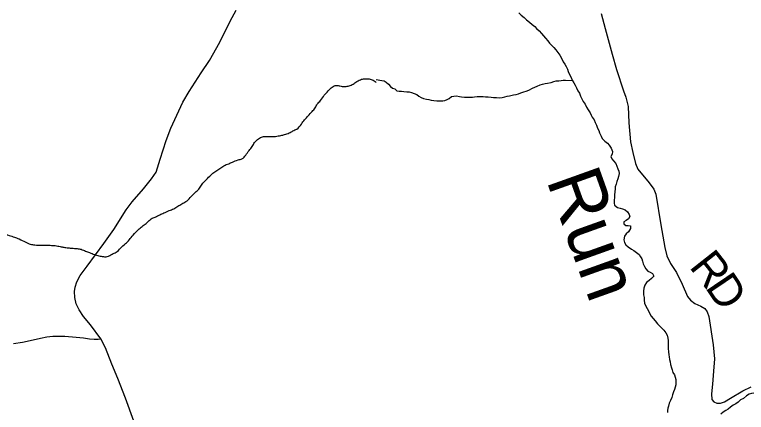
# Model space of a CAD drawing. Extents: x -13.7 to 34, y 0 to 32.3.
# Drawn here: x 28.447 to 29.728, y 16.87 to 17.566 of the extents above; entities that cross this region are included whole.
import ezdxf

# ---------------------------------------------------------------- set-up
doc = ezdxf.new("R2010")
doc.units = 0
for name, color, linetype in [('GM_X_County_Road', 7, 'Continuous'), ('GM_X_Minor_River', 7, 'Continuous'), ('GM_X_Minor_River_Text', 7, 'Continuous'), ('GM_X_Township_Road', 7, 'Continuous'), ('GM_X_Township_Road_Text', 7, 'Continuous')]:
    doc.layers.add(name, color=color, linetype=linetype)

msp = doc.modelspace()

# ---------------------------------------------------------------- linework, layer by layer
at = {"layer": 'GM_X_County_Road'}
msp.add_lwpolyline([(28.6553, 16.8546), (28.641, 16.8947), (28.6272, 16.9288), (28.617, 16.954), (28.6055, 16.9827), (28.5974, 16.9986), (28.5797, 17.0227), (28.567, 17.0378), (28.5598, 17.049), (28.5546, 17.0596), (28.5518, 17.0705), (28.5512, 17.0811), (28.5525, 17.0888), (28.5555, 17.0984), (28.5614, 17.1091), (28.5736, 17.1258), (28.6027, 17.165), (28.6205, 17.19), (28.6417, 17.2243), (28.6525, 17.2383), (28.6721, 17.2607), (28.6865, 17.2785), (28.6942, 17.2902), (28.7017, 17.3128), (28.7118, 17.3453), (28.7204, 17.3673), (28.7412, 17.4125), (28.7521, 17.4312), (28.7734, 17.4638), (28.788, 17.4853), (28.8058, 17.5175), (28.8243, 17.5543), (28.8345, 17.5735)], dxfattribs=at)
at = {"layer": 'GM_X_Minor_River'}
for points in [[(29.3294, 17.5691), (29.3336, 17.5649), (29.3385, 17.5607), (29.3427, 17.557), (29.3481, 17.5528), (29.353, 17.5483), (29.3572, 17.5452), (29.3606, 17.5414), (29.3648, 17.5377), (29.369, 17.5327), (29.3724, 17.5286), (29.3762, 17.5248), (29.38, 17.5199), (29.3831, 17.5161), (29.3865, 17.5123), (29.3907, 17.5085), (29.3941, 17.5043), (29.3976, 17.4998), (29.401, 17.4949), (29.4041, 17.4896), (29.4071, 17.4835), (29.4098, 17.4793), (29.4121, 17.4748), (29.4144, 17.4706), (29.4159, 17.4661), (29.4182, 17.4611)], [(29.0798, 17.4523), (29.0897, 17.4505), (29.0935, 17.4497), (29.0973, 17.4474), (29.1015, 17.444), (29.1046, 17.4399), (29.1084, 17.4372), (29.1122, 17.4357), (29.116, 17.4323), (29.1202, 17.4316), (29.1243, 17.4316), (29.1281, 17.4312), (29.1335, 17.4305), (29.1376, 17.4305), (29.1414, 17.4297), (29.1464, 17.4278), (29.1506, 17.4263), (29.1544, 17.4229), (29.1582, 17.4207), (29.1624, 17.4188), (29.1677, 17.4176), (29.1718, 17.4173), (29.176, 17.4161), (29.1806, 17.4154), (29.1859, 17.4147), (29.1916, 17.4147), (29.1962, 17.4151), (29.2, 17.4158), (29.2037, 17.4174), (29.2075, 17.4193), (29.2113, 17.4223), (29.2159, 17.4231), (29.2201, 17.4235), (29.2254, 17.4223), (29.2292, 17.422), (29.2341, 17.4212), (29.2387, 17.4212), (29.2428, 17.4216), (29.2482, 17.4216), (29.252, 17.422), (29.2565, 17.4224), (29.2607, 17.4228), (29.2668, 17.4224), (29.2713, 17.4221), (29.2759, 17.4217), (29.2812, 17.4213), (29.285, 17.4206), (29.2903, 17.4206), (29.2949, 17.4202), (29.3002, 17.4206), (29.3051, 17.4222), (29.3093, 17.4229), (29.3131, 17.4237), (29.3203, 17.4252), (29.3249, 17.426), (29.3287, 17.4272), (29.3332, 17.4291), (29.3381, 17.4306), (29.3423, 17.4321), (29.3472, 17.4336), (29.3533, 17.4371), (29.3575, 17.439), (29.3617, 17.4409), (29.367, 17.4428), (29.3708, 17.444), (29.3753, 17.4451), (29.3799, 17.4459), (29.3863, 17.447), (29.3909, 17.4489), (29.3947, 17.4497), (29.3996, 17.4501), (29.4034, 17.4505), (29.4072, 17.4509), (29.411, 17.4509), (29.4237, 17.4503)], [(29.4182, 17.4611), (29.4208, 17.4558), (29.4231, 17.4513), (29.4258, 17.4467), (29.4281, 17.4426), (29.4304, 17.4377), (29.4327, 17.4327), (29.4354, 17.4282), (29.4376, 17.4229), (29.4396, 17.4187), (29.4422, 17.4138), (29.4453, 17.4089), (29.448, 17.4039), (29.4506, 17.3994), (29.4541, 17.3941), (29.456, 17.3899), (29.4579, 17.3861), (29.4613, 17.3816), (29.4632, 17.377), (29.4655, 17.3721), (29.4674, 17.3672), (29.4693, 17.363), (29.4709, 17.3588), (29.4735, 17.3531), (29.4754, 17.349), (29.48, 17.3441), (29.4846, 17.341), (29.4876, 17.3372), (29.4911, 17.3323), (29.4937, 17.3263), (29.4926, 17.3217), (29.4907, 17.3175), (29.4923, 17.3137), (29.4953, 17.3099), (29.4995, 17.3054), (29.501, 17.3009), (29.5029, 17.2959), (29.5045, 17.2918), (29.5049, 17.288), (29.5037, 17.2823), (29.503, 17.2785), (29.5011, 17.2739), (29.4996, 17.269), (29.4981, 17.2644), (29.4981, 17.2606), (29.4973, 17.2561), (29.497, 17.25), (29.497, 17.2458), (29.4966, 17.2413), (29.4963, 17.236), (29.4967, 17.2322), (29.5024, 17.2284), (29.5069, 17.2273), (29.5111, 17.2261), (29.5157, 17.2242), (29.5195, 17.2208), (29.5225, 17.2163), (29.5237, 17.2125), (29.5214, 17.2087), (29.5172, 17.2057), (29.5134, 17.2034), (29.5131, 17.1996), (29.5169, 17.1965), (29.5207, 17.1969), (29.5252, 17.1962), (29.5249, 17.1916), (29.5215, 17.1859), (29.5173, 17.1821), (29.5146, 17.1779), (29.5135, 17.1719), (29.5147, 17.1673), (29.517, 17.1628), (29.5208, 17.1594), (29.5269, 17.1552), (29.5307, 17.1533), (29.5356, 17.1495), (29.5402, 17.1458), (29.5425, 17.142), (29.5448, 17.1382), (29.5459, 17.1344), (29.5474, 17.1295), (29.5497, 17.1249), (29.5516, 17.1211), (29.5554, 17.117), (29.5596, 17.1151), (29.5634, 17.1128), (29.5657, 17.1083), (29.5619, 17.1041), (29.5574, 17.1007), (29.5532, 17.0968), (29.5498, 17.0923), (29.5483, 17.0873), (29.5479, 17.0817), (29.548, 17.0752), (29.5487, 17.071), (29.5487, 17.0661), (29.5495, 17.0608), (29.5514, 17.057), (29.5541, 17.0513), (29.5564, 17.0475), (29.5583, 17.0434)], [(29.5583, 17.0434), (29.5614, 17.0381), (29.5644, 17.0339), (29.5682, 17.0297), (29.572, 17.0248), (29.5762, 17.0206), (29.5796, 17.0169), (29.5834, 17.0138), (29.5869, 17.0089), (29.5892, 17.0051), (29.5903, 16.9998), (29.5907, 16.9953), (29.5907, 16.9907), (29.5907, 16.9854), (29.5911, 16.9816), (29.5915, 16.9755), (29.5923, 16.9706), (29.5927, 16.9668), (29.5935, 16.9622), (29.5942, 16.9581), (29.595, 16.9535), (29.5969, 16.9478), (29.5981, 16.944), (29.5992, 16.9395), (29.6019, 16.9353), (29.6034, 16.9315), (29.6046, 16.927), (29.6046, 16.9224), (29.6042, 16.9179), (29.6031, 16.9137), (29.602, 16.9099), (29.6005, 16.9057), (29.5986, 16.9004), (29.5971, 16.8959), (29.5948, 16.8905), (29.5929, 16.886), (29.5914, 16.8807), (29.5903, 16.8769), (29.5895, 16.8731), (29.5899, 16.8693)], [(29.773, 16.8697), (29.7691, 16.8735), (29.7657, 16.8781), (29.7623, 16.8822), (29.7596, 16.8868), (29.7562, 16.8909), (29.7524, 16.8955), (29.7489, 16.9), (29.7448, 16.9027), (29.7406, 16.9034), (29.7368, 16.9027), (29.7326, 16.9015), (29.7281, 16.8985), (29.7228, 16.8943), (29.7178, 16.8916), (29.7133, 16.8878), (29.7091, 16.8848), (29.7049, 16.8821), (29.7, 16.8787), (29.6958, 16.8756), (29.6917, 16.8729), (29.6871, 16.8699), (29.683, 16.8669)]]:
    msp.add_lwpolyline(points, dxfattribs=at)
for points in [[(28.7326, 17.2304), (28.7392, 17.2347), (28.7465, 17.2387), (28.754, 17.2456), (28.761, 17.253), (28.7681, 17.2592), (28.7728, 17.2655), (28.7772, 17.2722), (28.7843, 17.2792), (28.7922, 17.2869), (28.7988, 17.292), (28.8061, 17.2967), (28.8131, 17.3014), (28.8216, 17.3049), (28.8281, 17.3078), (28.8378, 17.3116), (28.8447, 17.3137), (28.8513, 17.3199), (28.8573, 17.3281), (28.8625, 17.3351), (28.8669, 17.3422), (28.8735, 17.3484), (28.8809, 17.352), (28.8877, 17.3525), (28.8953, 17.3523), (28.9033, 17.3528), (28.9128, 17.3544), (28.9193, 17.356), (28.9274, 17.3588), (28.934, 17.3624), (28.9405, 17.3656), (28.9488, 17.3744), (28.9543, 17.3815), (28.9607, 17.3889), (28.9674, 17.3962), (28.9729, 17.4029), (28.9765, 17.4092), (28.9824, 17.4155), (28.9888, 17.4248), (28.9959, 17.4322), (29.0029, 17.4391), (29.0099, 17.442), (29.0163, 17.441), (29.0238, 17.44), (29.0307, 17.4409), (29.0376, 17.4433), (29.0442, 17.4477), (29.052, 17.452), (29.0592, 17.4536), (29.066, 17.4534), (29.0725, 17.452), (29.0799, 17.4472)], [(27.9877, 17.1483), (27.9955, 17.1534), (28.002, 17.1554), (28.01, 17.1555), (28.0172, 17.1568), (28.0265, 17.1611), (28.0334, 17.1639), (28.042, 17.1697), (28.049, 17.1748), (28.0563, 17.1798), (28.0619, 17.1869), (28.0694, 17.1954), (28.0749, 17.202), (28.0812, 17.209), (28.091, 17.2175), (28.098, 17.2237), (28.1062, 17.2299), (28.117, 17.2363), (28.1237, 17.2411), (28.1302, 17.245), (28.1387, 17.2482), (28.1468, 17.2525), (28.1533, 17.2541), (28.1617, 17.2558), (28.1694, 17.257), (28.1762, 17.2579), (28.1835, 17.2585), (28.1907, 17.2582), (28.1975, 17.2572), (28.2065, 17.255), (28.2152, 17.2532), (28.2235, 17.2514), (28.2302, 17.2493), (28.2374, 17.2479), (28.2446, 17.2469), (28.2517, 17.2448), (28.2581, 17.2431), (28.2649, 17.2413), (28.2731, 17.2384), (28.2806, 17.2355), (28.2892, 17.2299), (28.297, 17.2254), (28.3051, 17.2191), (28.3137, 17.2127), (28.3203, 17.2076), (28.3292, 17.2012), (28.3367, 17.1968), (28.3437, 17.1908), (28.3585, 17.1797), (28.3664, 17.1772), (28.3748, 17.1776), (28.3813, 17.1793), (28.3893, 17.1817), (28.3985, 17.1833), (28.405, 17.1839), (28.4133, 17.184), (28.4205, 17.1837), (28.428, 17.182), (28.4344, 17.1802), (28.4442, 17.1772), (28.4521, 17.1743), (28.4626, 17.1694), (28.4723, 17.1649), (28.4798, 17.1631), (28.4897, 17.1624), (28.4961, 17.1622), (28.5026, 17.1624), (28.509, 17.1622), (28.5177, 17.1615), (28.5264, 17.1601), (28.5328, 17.1587), (28.5404, 17.1577), (28.5468, 17.1571), (28.5559, 17.1564), (28.5631, 17.1551), (28.5709, 17.1521), (28.578, 17.1493), (28.5863, 17.1459), (28.5942, 17.1438), (28.6021, 17.1424), (28.6086, 17.1425), (28.6174, 17.1468), (28.6244, 17.15), (28.6318, 17.157), (28.6408, 17.165), (28.6475, 17.172), (28.6542, 17.1798), (28.6645, 17.1908), (28.6719, 17.1967), (28.6789, 17.2018), (28.6859, 17.2084), (28.6929, 17.2116), (28.7006, 17.2155), (28.7079, 17.2187), (28.7175, 17.2229), (28.7252, 17.2261), (28.7326, 17.2304)]]:
    msp.add_spline(points, degree=3, dxfattribs=at)
at = {"layer": 'GM_X_Township_Road'}
for points in [[(29.4734, 17.568), (29.4804, 17.5415), (29.493, 17.4967), (29.5006, 17.4698), (29.5125, 17.4326), (29.5168, 17.4214), (29.5206, 17.4052), (29.5221, 17.3766), (29.5252, 17.3433), (29.529, 17.3245), (29.5337, 17.3054), (29.5378, 17.2951), (29.5578, 17.2713), (29.5661, 17.2604), (29.5695, 17.2518), (29.5781, 17.1979), (29.585, 17.1581), (29.5883, 17.1438), (29.5952, 17.1305), (29.6057, 17.1143), (29.6152, 17.0943), (29.6248, 17.0724), (29.6298, 17.0659), (29.6376, 17.0605), (29.6479, 17.0559), (29.6552, 17.0514), (29.6591, 17.0457), (29.6619, 17.0376), (29.6698, 16.988), (29.6719, 16.9635), (29.6705, 16.942), (29.6684, 16.9189), (29.6667, 16.902), (29.6676, 16.8925), (29.6707, 16.8884), (29.6762, 16.886), (29.6824, 16.886), (29.6897, 16.8884), (29.7, 16.8945), (29.7217, 16.9075), (29.7363, 16.9146)], [(28.4445, 16.9904), (28.4603, 16.9926), (28.479, 16.9965), (28.4921, 16.9995), (28.5033, 17.0019), (28.5138, 17.0031), (28.525, 17.0033), (28.5346, 17.0029), (28.5544, 17.0012), (28.567, 17.0001), (28.5776, 16.9987), (28.5862, 16.9977), (28.5927, 16.9979), (28.5974, 16.9986)]]:
    msp.add_lwpolyline(points, dxfattribs=at)

# ---------------------------------------------------------------- texts
at = {"layer": 'GM_X_Minor_River_Text'}
msp.add_text('Run', height=0.09471, rotation=289.686, dxfattribs=at).set_placement((29.3771, 17.2765))
at = {"layer": 'GM_X_Township_Road_Text'}
for s, rotation, p in [('R', 308.2368, (29.6264, 17.1245)), ('D', 304.0457, (29.6546, 17.0887))]:
    msp.add_text(s, height=0.0568, rotation=rotation, dxfattribs=at).set_placement(p)

doc.saveas('drawing.dxf')
